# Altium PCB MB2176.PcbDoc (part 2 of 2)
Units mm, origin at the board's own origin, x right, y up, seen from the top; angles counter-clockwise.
Board outline 43 x 47 mm, 2 copper layers (Top Layer, Bottom Layer), stack 0.996 mm thick; 80 components, 70 nets, 345 pads, 549 vias.
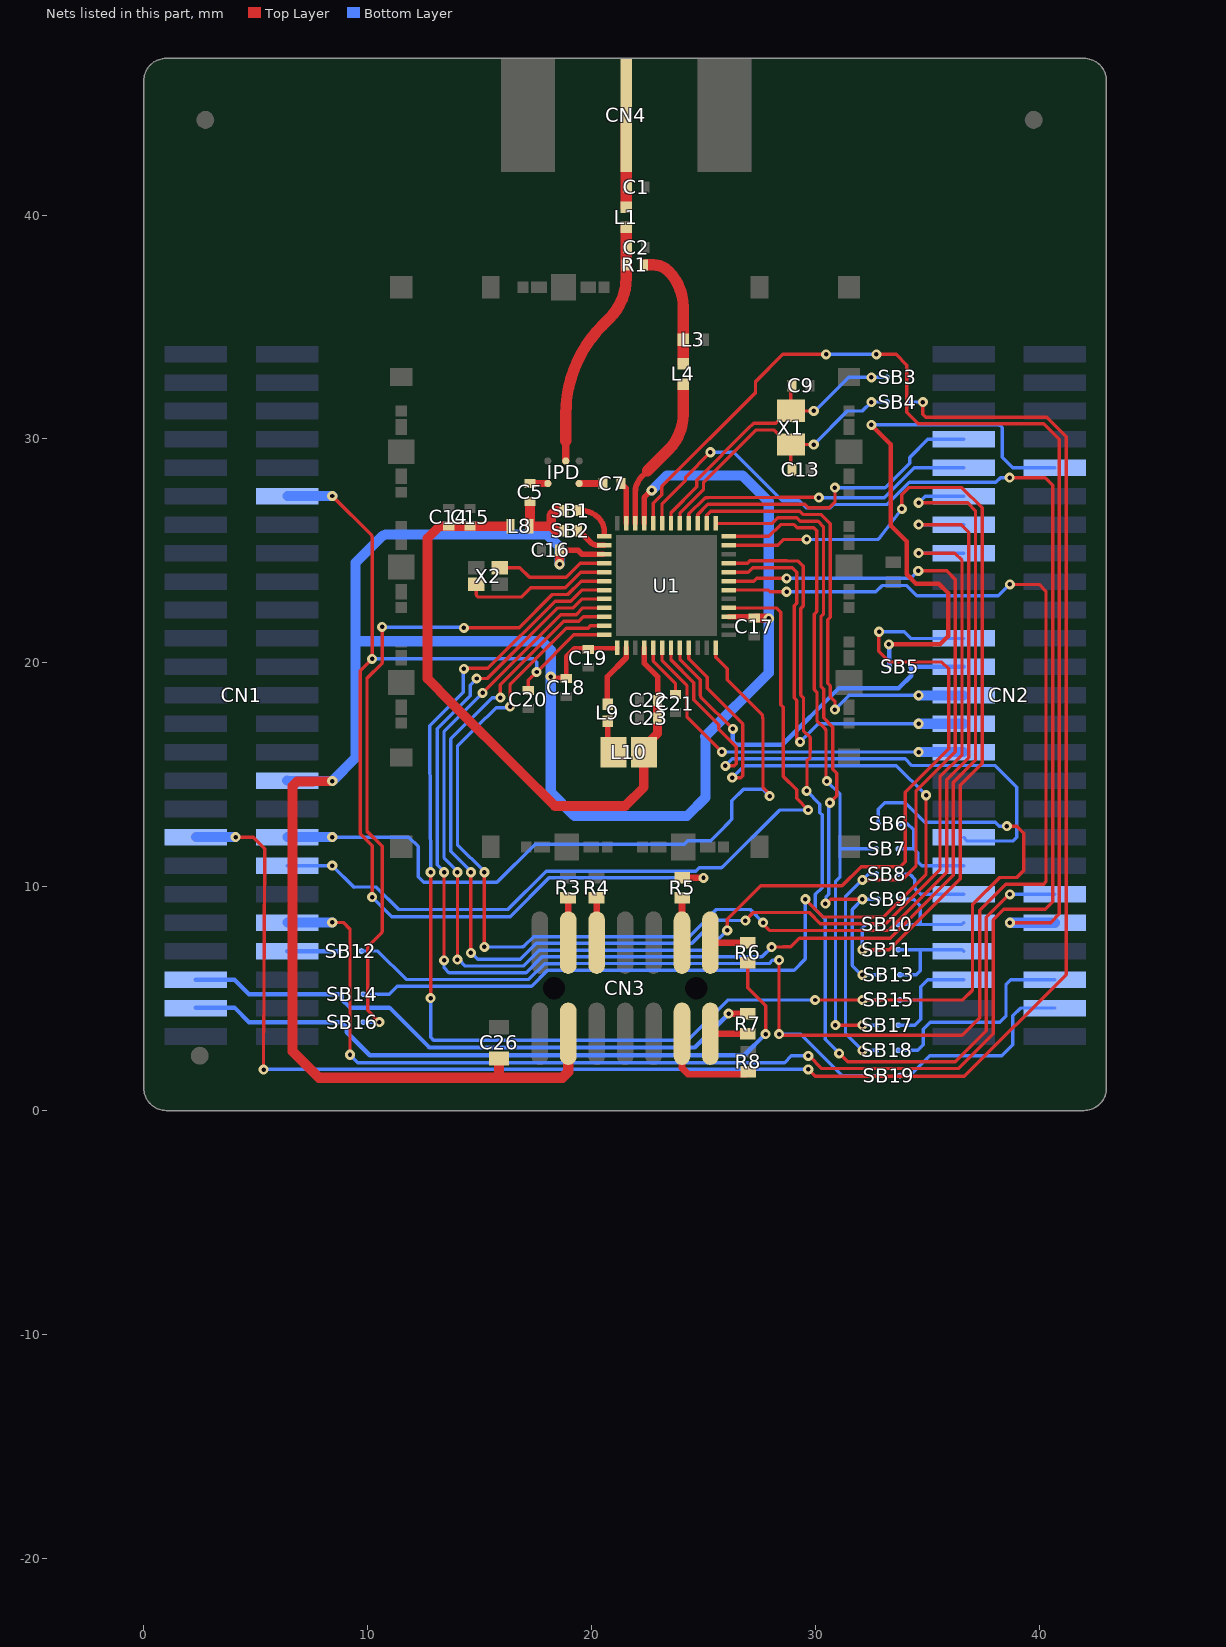
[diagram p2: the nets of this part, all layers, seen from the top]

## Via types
v1: diameter 0.45, hole 0.2, Top Layer to Bottom Layer, tented both sides, 549 vias

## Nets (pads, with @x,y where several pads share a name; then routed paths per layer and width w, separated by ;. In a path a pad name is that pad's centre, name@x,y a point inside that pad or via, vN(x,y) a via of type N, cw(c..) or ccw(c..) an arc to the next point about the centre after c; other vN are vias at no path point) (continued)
GPIO16/OSC32_OUT: CN1.35 SB4.2 | length 83.1
  Top Layer w0.15: v1(4.101,12.21) 4.884,12.21 5.4,11.695 v1(5.35,1.825) ; v1(29.681,1.84) 29.996,1.525 36.65,1.525 41.2,6.075 41.2,30.102 40.327,30.975 34.932,30.975 34.8,31.107 v1(34.8,31.647)
  Bottom Layer w0.15: v1(5.35,1.825) 5.365,1.84 v1(29.681,1.84) ; SB4.2@34.1,31.647 SB4.2@34.175,31.647 v1(34.8,31.647)
  Bottom Layer w0.45: CN1.35@2.343,12.21 v1(4.101,12.21)
GPIO17: CN1.36 U1.48 | length 33.4
  Top Layer w0.15: U1.48@25.55,20.675 25.55,20.25 26.063,19.737 26.063,19.239 27.597,17.705 cw(c27.491,17.599) 27.638,17.623 27.654,17.528 cw(c27.21,17.455) 27.66,17.455 27.66,15.246 27.66,14.417 27.954,14.123 v1(27.954,14.042)
  Bottom Layer w0.15: v1(8.42,12.21) 11.84,12.21 12.254,11.796 12.254,10.439 12.5,10.193 15.778,10.193 17.479,11.894 24.15,11.894 24.299,12.043 25.319,12.043 25.975,12.699 ; v1(27.954,14.042) 27.641,14.355 26.788,14.355 26.268,13.835 26.268,13.011 26.137,12.88 ; 25.975,12.699 26.137,12.861 26.137,12.88 ; 25.975,12.699 25.975,12.718 26.137,12.88
  Bottom Layer w0.45: CN1.36@6.413,12.21 v1(8.42,12.21)
GPIO18: CN1.38 U1.4 | length 37.7
  Top Layer w0.15: U1.4@26.125,22.45 28.25,22.45 28.449,22.251 28.449,18.125 28.56,18.014 28.56,14.921 29.16,14.321 29.16,13.94 v1(29.677,13.424)
  Bottom Layer w0.15: CN1.38@6.413,10.94 v1(8.42,10.94) 9.39,9.97 9.401,9.982 10.385,9.982 11.387,8.98 16.262,8.98 17.976,10.694 24.666,10.694 24.815,10.843 25.753,10.843 ccw(c25.753,10.993) 25.858,10.886 25.901,10.929 ccw(c25.692,11.143) 25.904,10.931 28.397,13.424 v1(29.677,13.424)
GPIO21: CN1.42 U1.19 | length 86.2
  Top Layer w0.15: v1(8.42,8.4) 8.91,8.4 9.211,8.099 v1(9.211,2.491) ; U1.19@23.15,26.225 23.15,27.097 24.2,28.146 24.2,28.297 v1(25.306,29.404) ; v1(29.681,2.44) 29.717,2.44 30.283,1.875 36.375,1.875 37.938,3.438 37.938,8.513 38.413,8.988 40.261,8.988 40.6,9.326 40.6,27.932 40.259,28.273 v1(38.672,28.273)
  Bottom Layer w0.15: v1(9.211,2.491) 9.561,2.14 28.621,2.14 28.921,2.44 v1(29.681,2.44) ; v1(25.306,29.404) 26.36,29.404 28.518,27.246 29.271,27.246 29.592,26.925 30.663,26.925 30.809,27.071 33.21,27.071 34.201,28.062 38.059,28.062 38.269,28.273 v1(38.672,28.273)
  Bottom Layer w0.45: CN1.42@6.413,8.4 v1(8.42,8.4)
GPIO22: CN1.44 SB12.2 | length 2.4
  Bottom Layer w0.2: CN1.44@6.401,7.118 6.408,7.125 SB12.2@8.75,7.125
GPIO23/VCP1_RX: CN1.45 R7.1 SB14.1 | length 26.7
  Top Layer w0.3: v1(26.125,4.325) R7.1@26.975,4.325
  Bottom Layer w0.2: CN1.45@2.331,5.848 4.052,5.848 4.7,5.2 SB14.1@8.825,5.2 8.835,5.19 8.835,4.974 9.211,4.598 10.523,4.598 10.525,4.6 10.975,4.6 12.76,2.815 24.615,2.815 v1(26.125,4.325)
GPIO24/VCP1_TX: CN1.47 R6.2 SB16.1 | length 30.4
  Top Layer w0.15: R6.2@26.975,6.6 26.975,5.478 27.775,4.678 v1(27.775,3.417)
  Bottom Layer w0.2: CN1.47@2.331,4.598 4.052,4.598 4.7,3.95 SB16.1@8.825,3.95 9.063,3.712 9.063,3.496 10.094,2.465 26.824,2.465 v1(27.775,3.417)
GPIO28: CN2.7 U1.15 | length 14.3
  Top Layer w0.15: U1.15@24.75,26.225 24.75,26.624 25.201,27.075 29.534,27.075 29.684,26.925 30.62,26.925 30.875,27.18 v1(30.875,27.821)
  Bottom Layer w0.15: v1(30.875,27.821) 33.111,27.821 34.21,28.921 34.21,29.17 35.018,29.978 CN2.7@36.621,29.978
GPIO29: CN2.9 U1.16 | length 13.5
  Top Layer w0.15: U1.16@24.35,26.225 24.35,26.649 25.032,27.331 ; 25.032,27.332 cw(c25.137,27.224) 25.135,27.374 25.198,27.375 cw(c25.201,27.075) 25.2,27.375 28.448,27.388 30.145,27.388 v1(30.158,27.375)
  Bottom Layer w0.15: v1(30.158,27.375) 30.162,27.371 33.085,27.371 34.422,28.708 CN2.9@36.621,28.708
GPIO30: CN2.10 SB5.1 | length 25
  Top Layer w0.2: v1(32.5,30.625) 33.358,29.767 33.358,26.139 34.075,25.422 34.075,23.952 34.491,23.536 35.51,23.536 35.926,23.119 35.926,21.184 35.564,20.823 v1(33.283,20.823)
  Bottom Layer w0.15: v1(32.5,30.625) 38.166,30.625 cw(c38.166,30.475) 38.273,30.581 38.347,30.506 38.347,29.184 38.824,28.708 CN2.10@40.691,28.708
  Bottom Layer w0.2: v1(33.283,20.823) 33.292,20.814 33.292,19.833 SB5.1@33.3,19.825
GPIO31: CN2.11 U1.32 | length 67.1
  Top Layer w0.15: v1@13.412,10.643 13.412,6.745 13.413,6.744 v1(13.413,6.706) ; v1(14.869,19.299) 15.349,19.299 18.5,22.45 19.19,22.45 19.59,22.85 U1.32@20.575,22.85 ; v1(28.047,7.298) 28.568,7.311 cw(c28.572,7.161) 28.572,7.311 28.9,7.311 29.289,7.7 33.352,7.7 36.164,10.512 36.164,14.653 37.151,15.639 37.151,26.8 36.801,27.15 v1(34.614,27.15)
  Bottom Layer w0.15: v1(13.412,10.643) 13.412,10.679 13.112,10.979 13.112,17.057 14.575,18.52 14.575,19.005 v1(14.869,19.299) ; v1(13.413,6.706) 13.413,6.371 13.631,6.153 17.075,6.153 17.787,6.865 27.615,6.865 v1(28.047,7.298) ; v1(34.614,27.15) 34.902,27.438 CN2.11@36.621,27.438
GPIO33: CN2.13 U1.35 | length 61.6
  Top Layer w0.15: v1(15.212,7.305) v1(15.212,10.643) ; v1(16.366,18.039) 16.375,18.435 ccw(c15.925,18.446) 16.375,18.459 16.36,18.971 cw(c16.51,18.975) 16.404,19.081 18.873,21.55 19.848,21.55 19.948,21.65 U1.35@20.575,21.65 ; v1(27.669,8.395) 27.669,8.321 27.948,8.042 33.27,8.042 35.864,10.636 35.864,14.777 36.851,15.764 36.851,25.841 36.524,26.168 v1(34.614,26.168)
  Bottom Layer w0.15: v1(15.212,10.643) 15.212,10.679 14.012,11.879 14.012,16.267 14.859,17.114 14.859,17.118 15.737,17.996 16.323,17.996 v1(16.366,18.039) ; v1@15.25,7.305 16.896,7.308 ccw(c16.895,7.458) 17.001,7.352 17.415,7.765 24.302,7.765 ccw(c24.302,7.915) 24.408,7.809 25.578,8.98 27.085,8.98 v1(27.669,8.395) ; v1(34.614,26.168) CN2.13@36.621,26.168
GPIO34: CN2.15 U1.34 | length 60.8
  Top Layer w0.15: v1(14.612,7.043) v1(14.612,10.643) ; v1(15.925,18.446) 15.925,19.026 18.749,21.85 19.439,21.85 19.639,22.05 20.075,22.05 U1.34@20.575,22.05 ; v1(26.869,8.488) 27.227,8.845 29.718,8.845 30.221,8.342 33.084,8.342 ccw(c33.084,8.492) 33.19,8.386 35.564,10.761 35.564,14.901 36.551,15.888 36.551,24.57 36.222,24.898 v1(34.614,24.898)
  Bottom Layer w0.15: v1(14.612,10.643) 14.612,10.679 13.712,11.579 13.712,16.596 15.562,18.446 v1(15.925,18.446) ; v1@14.692,7.043 14.692,6.984 14.917,6.759 15.276,6.759 15.282,6.753 16.827,6.753 17.539,7.465 24.488,7.465 25.515,8.492 26.125,8.492 26.13,8.488 v1(26.869,8.488) ; v1(34.614,24.898) CN2.15@36.621,24.898
GPIO37: CN2.21 U1.33 | length 59.8
  Top Layer w0.15: v1(14.012,6.744) v1(14.012,10.643) ; v1(15.138,18.658) 15.138,18.663 18.624,22.15 19.314,22.15 19.614,22.45 U1.33@20.575,22.45 ; v1(26.063,8.042) 26.063,8.541 27.557,10.035 31.188,10.035 32.044,10.891 33.788,10.891 34.012,11.115 34.012,14.214 35.951,16.152 35.951,19.728 35.646,20.033 33.367,20.033 cw(c33.367,20.183) 33.244,20.097 32.833,20.508 32.833,21.373 v1(32.848,21.388)
  Bottom Layer w0.15: v1(14.012,10.643) 14.012,10.679 13.412,11.279 13.412,16.933 v1(15.138,18.658) ; v1@14.083,6.744 14.083,6.73 14.359,6.453 15.112,6.453 15.118,6.459 ccw(c15.158,6.603) 15.158,6.453 16.951,6.453 17.663,7.165 25.186,7.165 v1(26.063,8.042) ; v1(32.848,21.388) 33.965,21.388 34.265,21.088 CN2.21@36.621,21.088
GPIO39: CN2.23 SB5.2 U1.44 | length 17.2
  Top Layer w0.15: U1.44@23.95,20.675 23.95,20.15 24.26,19.84 24.263,19.84 24.7,19.403 24.7,19.4 24.863,19.237 24.863,18.552 ccw(c25.013,18.552) 24.907,18.445 v1(26.31,17.052)
  Bottom Layer w0.2: v1(26.31,17.052) 26.31,16.47 26.44,16.34 28.521,16.34 31.054,18.873 33.725,18.873 34.275,19.423 SB5.2@34.275,19.818 ; SB5.2@34.275,19.825 SB5.2@34.275,19.818 ; CN2.23@36.621,19.818 SB5.2@34.275,19.818
GPIO41: CN2.25 U1.14 | length 20.7
  Top Layer w0.15: U1.14@25.15,26.225 25.15,26.599 25.326,26.775 29.295,26.775 29.445,26.625 30.241,26.625 30.66,26.206 30.66,22.037 30.549,21.926 30.549,19.086 30.67,18.965 30.67,18.482 30.875,18.277 v1(30.875,17.907)
  Bottom Layer w0.15: v1(30.875,17.907) 31.516,18.548 v1(34.614,18.548)
  Bottom Layer w0.45: v1(34.614,18.548) CN2.25@36.621,18.548
GPIO42: CN2.27 U1.8 | length 18.6
  Top Layer w0.15: U1.8@26.125,24.05 26.992,24.05 27.192,24.25 28.61,24.25 28.611,24.248 28.962,24.248 29.16,24.05 29.16,22.665 29.049,22.554 29.049,18.434 29.168,18.315 29.168,16.615 v1(29.318,16.465)
  Bottom Layer w0.15: v1(29.318,16.465) 30.131,17.278 v1(34.614,17.278)
  Bottom Layer w0.45: v1(34.614,17.278) CN2.27@36.621,17.278
GPIO44: CN2.29 U1.42 | length 16.6
  Top Layer w0.15: U1.42@23.15,20.675 23.15,20.101 24.263,18.989 24.263,17.584 v1(25.825,16.022)
  Bottom Layer w0.15: v1(25.825,16.022) 25.832,16.015 34.607,16.015 v1(34.614,16.008)
  Bottom Layer w0.45: v1(34.614,16.008) CN2.29@36.621,16.008
GPIO47: CN2.35 U1.43 | length 25.3
  Top Layer w0.15: U1.43@23.55,20.675 23.55,20.126 24.563,19.113 24.563,18.347 25.675,17.235 25.675,17.041 26.46,16.256 26.46,15.483 26.372,15.395 v1(25.979,15.395)
  Bottom Layer w0.15: v1(25.979,15.395) 26.292,15.708 34.016,15.708 34.314,15.41 38.032,15.41 39,14.442 39,12.214 38.824,12.037 36.782,12.037 CN2.35@36.621,12.198
GPIO49: CN2.37 SB6.2 SB7.1 | length 5
  Bottom Layer w0.15: SB6.2@33.7,12.812 34.114,12.812 34.394,12.532 34.394,11.688 ; SB7.1@33.775,11.688 34.394,11.688 ; CN2.37@36.621,10.928 34.757,10.928 34.569,11.115 34.569,11.512 34.394,11.688
GPIO50: CN2.39 SB8.1 | length 3.5
  Bottom Layer w0.15: SB8.1@33.7,10.563 34.21,10.563 34.275,10.498 34.439,10.334 34.439,9.918 34.699,9.658 CN2.39@36.621,9.658
GPIO51: CN2.40 U1.9 | length 42.2
  Top Layer w0.15: U1.9@26.125,24.45 26.968,24.45 27.068,24.55 28.734,24.55 28.736,24.548 29.222,24.548 29.46,24.31 29.46,22.536 29.349,22.425 29.349,18.558 29.468,18.44 29.468,16.964 29.768,16.664 29.768,16.064 29.76,16.056 29.76,15.762 29.624,15.626 29.624,14.293 v1(29.61,14.279) ; v1(31.056,2.556) 31.394,2.218 ccw(c31.5,2.325) 31.499,2.175 36.251,2.175 37.638,3.562 37.638,8.637 38.659,9.658 v1(38.684,9.658)
  Bottom Layer w0.15: v1(29.61,14.279) 30.2,13.689 30.2,13.308 30.3,13.208 30.3,9.958 30,9.658 30,8.981 30.439,8.542 30.439,3.174 v1(31.056,2.556) ; v1(38.684,9.658) CN2.40@40.691,9.658
GPIO52: CN2.41 SB9.2 SB10.1 | length 4.8
  Bottom Layer w0.15: SB10.1@33.7,8.313 34.687,8.313 ; SB9.2@33.775,9.437 34.394,9.437 34.687,9.144 34.687,8.313 ; CN2.41@36.621,8.388 36.546,8.313 34.687,8.313
GPIO53: CN2.42 U1.20 | length 50.8
  Top Layer w0.15: U1.20@22.75,26.225 22.75,27.121 23.142,27.513 23.142,27.828 cw(c23.292,27.827) 23.185,27.932 27.282,32.029 ; v1(30.475,33.775) 28.539,33.775 27.325,32.561 27.325,32.135 ; v1(32.725,33.775) 33.613,33.775 34.087,33.3 34.087,31.182 34.594,30.675 40.203,30.675 40.9,29.978 40.9,8.779 40.509,8.388 v1(38.684,8.388) ; 27.282,32.029 ccw(c27.175,32.135) 27.325,32.135 ; 27.282,32.029 27.325,32.073 27.325,32.135
  Bottom Layer w0.15: v1(30.475,33.775) v1(32.725,33.775)
  Bottom Layer w0.45: v1(38.684,8.388) CN2.42@40.691,8.388
GPIO54: CN2.43 SB11.1 SB13.2 | length 4.9
  Bottom Layer w0.15: SB11.1@33.7,7.187 34.7,7.187 ; SB13.2@33.775,6.062 34.513,6.062 34.687,6.237 34.687,7.175 34.7,7.187 ; CN2.43@36.621,7.118 36.552,7.187 34.7,7.187
GPIO55: CN2.45 SB15.2 SB17.1 | length 5.5
  Bottom Layer w0.15: SB17.1@33.7,3.812 34.439,3.812 34.7,4.073 34.7,4.95 ; SB15.2@33.775,4.938 34.687,4.938 34.7,4.95 ; CN2.45@36.621,5.848 35.018,5.848 34.7,5.53 34.7,4.95
GPIO56: CN2.46 SB18.1 | length 9.5
  Bottom Layer w0.15: SB18.1@33.7,2.688 34.569,2.688 34.813,2.931 34.813,3.637 35.125,3.95 38.237,3.95 38.517,4.23 38.517,5.642 38.723,5.848 CN2.46@40.691,5.848
GPIO57: CN2.48 SB19.2 | length 8.9
  Bottom Layer w0.15: SB19.2@33.775,1.562 34.218,1.562 35.106,2.45 38.325,2.45 38.817,2.942 38.817,4.233 39.162,4.578 CN2.48@40.691,4.578
NetC1_2: C1.2 CN4.1 L1.2 | length 4.1
  Top Layer w0.51: L1.2@21.55,40.35 21.55,41.25 CN4.1@21.55,44.46
NetC2_2: C2.2 IPD.4 L1.1 R1.2 | length 11.2
  Top Layer w0.32: IPD.4@18.848,29.011 18.848,29.901
  Top Layer w0.51: 18.848,29.921 18.848,31.105 ; 18.849,31.106 cw(c24.472,31.106) 20.496,35.082 20.806,35.392 ccw(c19.01,37.188) 21.55,37.188 21.55,37.775 21.55,38.55 L1.1@21.55,39.45
NetC5_1: C5.1 L8.2 SB1.2 SB2.2 | length 3.6
  Top Layer w0.43: L8.2@17.25,26.1 17.254,26.104 17.254,27.047 C5.1@17.258,27.051 ; L8.2@17.275,26.1 18.193,26.1 ; SB2.2@18.698,25.9 18.393,25.9 18.193,26.1 ; SB1.2@18.724,26.8 18.401,26.8 18.193,26.592 18.193,26.1
NetC5_2: C5.2 IPD.1 | length 0.7
  Top Layer w0.32: C5.2@17.318,28.011 IPD.1@18.049,28.011
NetC7_1: C7.1 U1.23 | length 1.9
  Top Layer w0.25: C7.1@21.359,28.008 21.359,27.983 21.55,27.792 U1.23@21.55,26.225
NetC7_2: C7.2 IPD.2 | length 1
  Top Layer w0.32: IPD.2@19.449,28.011 20.456,28.011 C7.2@20.459,28.008
NetC9_2: C9.2 SB3.1 U1.18 X1.2 | length 14.1
  Top Layer w0.15: U1.18@23.55,26.225 23.55,26.704 24.7,27.854 24.7,28.161 26.988,30.448 27.239,30.7 28.237,30.7 28.35,30.813 28.35,30.825 28.775,31.25 X1.2@28.9,31.25 ; C9.2@28.9,32.375 X1.2@28.9,31.25 ; v1@30.075,31.25 X1.2@28.9,31.25
  Bottom Layer w0.15: v1(29.925,31.25) 30,31.25 31.497,32.747 v1(32.5,32.747) SB3.1@33.2,32.747
NetC13_2: C13.2 SB4.1 U1.17 X1.1 | length 13.6
  Top Layer w0.15: U1.17@23.95,26.225 23.95,26.68 25,27.73 25,28.036 27.364,30.4 28.149,30.4 28.35,30.199 28.35,30.175 28.775,29.75 X1.1@28.9,29.75 ; C13.2@28.9,28.625 X1.1@28.9,29.75 ; v1(29.925,29.75) X1.1@28.9,29.75
  Bottom Layer w0.15: v1(29.925,29.75) 31.422,31.247 32.1,31.247 v1(32.5,31.647) SB4.1@33.2,31.647
NetC21_2: C21.2 U1.41 | length 2.5
  Top Layer w0.15: U1.41@22.75,20.675 22.75,20.077 23.75,19.077 C21.2@23.75,18.625
NetCN3_4: CN3.4 R3.1 | length 2
  Top Layer w0.3: R3.1@18.95,9.5 18.96,9.49 CN3.4@18.96,7.5
NetCN3_6: CN3.6 R4.1 | length 2
  Top Layer w0.3: R4.1@20.225,9.5 20.23,9.495 CN3.6@20.23,7.5
NetCN3_11: CN3.11 R8.2 | length 4.7
  Top Layer w0.3: CN3.11@24.04,3.43 24.04,1.897 24.312,1.625 26.903,1.625 R8.2@27.003,1.725 ; R8.2@26.914,1.814 R8.2@26.928,1.828
NetCN3_12: CN3.12 R5.1 | length 2
  Top Layer w0.3: CN3.12@24.04,7.5 24.04,9.49 R5.1@24.05,9.5
NetCN3_13: CN3.13 R7.2 | length 1.7
  Top Layer w0.3: CN3.13@25.31,3.43 25.315,3.425 R7.2@26.975,3.425
NetCN3_14: CN3.14 R6.1 | length 1.7
  Top Layer w0.3: CN3.14@25.31,7.5 R6.1@26.975,7.5
NetL3_1: L3.1 L4.2 R1.1 | length 5.4
  Top Layer w0.51: R1.1@22.45,37.775 22.766,37.775 cw(c22.766,36.836) 23.43,37.5 cw(c21.813,35.883) 24.1,35.883 L3.1@24.1,34.425 L4.2@24.1,33.375
NetL4_1: L4.1 U1.22 | length 6.9
  Top Layer w0.25: U1.22@21.95,26.225 21.95,27.601 cw(c22.974,27.601) 22.25,28.325 22.5,28.575
  Top Layer w0.51: 22.5,28.575 23.43,29.505 ccw(c21.813,31.122) 24.1,31.122 L4.1@24.1,32.425
NetL9_1: L9.1 U1.38 | length 2.9
  Top Layer w0.25: L9.1@20.725,18.152 20.707,18.17 20.707,19.382 21.55,20.225 U1.38@21.55,20.675
NetL9_2: L9.2 L10.2 | length 1.5
  Top Layer w0.25: L9.2@20.725,17.394 20.725,16.27 L10.2@20.987,16.008
NetSB1_1: SB1.1 U1.25 | length 1.9
  Top Layer w0.25: SB1.1@19.375,26.8 19.528,26.8 cw(c19.528,25.69) 20.312,26.475 cw(c19.679,25.841) 20.575,25.841 U1.25@20.575,25.694
NetSB2_1: SB2.1 U1.26 | length 1.4
  Top Layer w0.25: SB2.1@19.375,25.9 cw(c19.375,25.746) 19.484,25.855 19.945,25.394 ccw(c20.292,25.74) 20.292,25.25 U1.26@20.575,25.25
NetSB6_1: SB6.1 SB15.1 U1.31 | length 67
  Top Layer w0.15: v1(12.812,5.025) v1(12.812,10.643) ; v1(14.301,19.725) 14.324,19.749 15.374,19.749 18.376,22.75 19.066,22.75 19.566,23.25 20.002,23.25 U1.31@20.575,23.25 ; v1(29.989,4.938) 32.033,4.923 ccw(c32.036,5.073) v1(32.1,4.938) ; v1(32.1,4.938) 36.593,4.938 37.017,5.361 37.017,9.192 38.234,10.409 39,10.409 39.312,10.722 39.312,12.386 39,12.699 38.551,12.699 v1(38.55,12.7)
  Bottom Layer w0.15: v1(12.812,5.025) 12.812,3.269 12.941,3.14 24.304,3.14 26.101,4.938 v1(29.989,4.938) ; v1(12.812,10.643) 12.781,16.461 12.781,17.181 14.275,18.675 14.275,19.699 v1(14.301,19.725) ; v1(32.1,4.938) SB15.1@32.8,4.938 ; SB6.1@32.8,12.812 32.8,13.45 33.1,13.75 34.007,13.75 34.884,12.873 38.029,12.873 38.202,12.7 v1(38.55,12.7)
NetSB7_2: SB7.2 SB17.2 U1.12 | length 30.4
  Top Layer w0.15: U1.12@26.125,25.65 27.924,25.65 28.449,26.175 29.047,26.175 29.197,26.025 29.935,26.025 30.06,25.9 30.06,22.288 29.949,22.177 29.949,18.807 30.07,18.686 30.07,17.411 30.431,17.05 cw(c30.325,16.944) 30.475,16.944 30.475,14.749 v1(30.51,14.714) ; v1(30.892,3.814) v1(32.1,3.812)
  Bottom Layer w0.15: v1(30.51,14.714) 31.1,14.124 31.1,11.688 ; v1(30.892,3.814) 30.9,3.822 30.9,10.234 31.1,10.434 31.1,11.688 ; v1(32.1,3.812) SB17.2@32.725,3.812 ; SB7.2@32.725,11.688 31.1,11.688
NetSB8_2: SB8.2 SB18.2 U1.7 | length 36.3
  Top Layer w0.15: U1.7@26.125,23.65 27.251,23.65 27.375,23.774 v1(28.71,23.774) ; v1(32.1,10.3) 33.882,10.3 34.492,10.91 34.492,14.269 36.251,16.028 36.251,23.721 35.867,24.105 v1(34.594,24.105)
  Bottom Layer w0.15: v1(28.71,23.774) 34.264,23.774 v1(34.594,24.105) ; SB18.2@32.725,2.688 v1(32.1,2.688) 31.342,3.445 31.342,9.542 v1(32.1,10.3) 32.363,10.563 SB8.2@32.725,10.563
NetSB9_1: SB9.1 SB13.1 U1.13 | length 29.4
  Top Layer w0.15: U1.13@25.55,26.225 28.075,26.225 28.325,26.475 29.171,26.475 29.321,26.325 30.117,26.325 30.36,26.082 30.36,22.161 30.249,22.05 30.249,18.942 30.37,18.821 30.37,17.535 30.775,17.13 30.775,15.25 30.96,15.064 30.96,14.06 v1(30.65,13.75) ; v1(30.45,9.244) 30.488,9.244 30.681,9.437 v1(32.1,9.437)
  Bottom Layer w0.15: v1(30.45,9.244) 30.476,9.27 30.476,9.544 30.6,9.669 30.6,13.699 v1(30.65,13.75) ; SB13.1@32.8,6.062 v1(32.1,6.062) 32.055,6.062 31.642,6.476 31.642,8.98 v1(32.1,9.437) SB9.1@32.8,9.437
NetSB10_2: SB10.2 SB11.2 U1.11 | length 38.2
  Top Layer w0.15: U1.11@26.125,25.25 28.329,25.25 28.588,25.508 v1(29.61,25.508) ; v1(32.1,7.18) 33.295,7.18 36.464,10.349 36.464,14.529 37.451,15.515 37.451,26.924 36.547,27.828 34.176,27.828 33.86,27.512 v1(33.86,26.875)
  Bottom Layer w0.15: v1(29.61,25.508) 32.735,25.508 ccw(c32.735,25.658) 32.853,25.567 v1(33.86,26.875) ; SB11.2@32.725,7.187 32.721,7.184 32.104,7.184 v1(32.1,7.18) 32.1,8.137 32.275,8.313 SB10.2@32.725,8.313
NetSB12_1: SB12.1 SB19.1 U1.6 | length 73.4
  Top Layer w0.15: U1.6@26.125,23.25 27.897,23.25 27.973,23.174 v1(28.71,23.174) ; v1(28.375,6.715) v1(28.375,3.417) 28.429,3.363 36.55,3.363 37.338,4.15 37.338,8.948 38.498,10.108 40.197,10.108 40.3,10.211 40.3,23.193 39.993,23.5 v1(38.687,23.5)
  Bottom Layer w0.15: SB12.1@9.725,7.125 10.449,7.125 11.721,5.853 17.2,5.853 17.909,6.562 19.074,6.562 19.077,6.565 27.935,6.565 28.075,6.706 v1@28.3,6.715 ; v1(28.375,3.417) 29.341,3.417 31.195,1.562 SB19.1@32.8,1.562 ; v1(28.71,23.174) 32.699,23.174 32.975,23.45 34.075,23.45 34.538,22.988 38.175,22.988 v1(38.687,23.5)
NetSB14_2: SB14.2 U1.45 | length 49.8
  Top Layer w0.15: U1.45@24.35,20.675 24.35,20.177 25.163,19.364 25.163,18.866 26.76,17.268 26.76,14.956 26.672,14.868 v1(26.287,14.868) ; v1(29.55,9.437) 30.345,8.642 33.021,8.642 34.942,10.563 v1(34.942,14.083)
  Bottom Layer w0.15: SB14.2@9.8,5.2 10.975,5.2 11.325,5.55 17.321,5.55 18.033,6.262 21.37,6.262 21.373,6.265 29.047,6.265 29.55,6.769 v1(29.55,9.437) ; v1(26.287,14.868) 26.826,15.408 27.399,15.408 33.617,15.408 v1(34.942,14.083)
NetSB16_2: SB16.2 U1.30 | length 30.2
  Top Layer w0.15: v1(10.525,3.95) 10,4.475 10,7.311 10.605,7.916 ccw(c10.499,8.023) 10.649,8.023 10.649,11.806 9.971,12.485 9.971,19.31 10.649,19.989 v1(10.649,21.6) ; v1(14.301,21.562) 16.764,21.562 18.252,23.05 18.942,23.05 19.542,23.65 U1.30@20.575,23.65
  Bottom Layer w0.15: SB16.2@9.8,3.95 v1(10.525,3.95) ; v1(10.649,21.6) 10.668,21.581 14.282,21.581 v1(14.301,21.562)
NetU1_28: U1.28 X2.3 | length 5.1
  Top Layer w0.15: X2.3@15.905,24.25 16.797,24.25 17.229,23.818 18.861,23.818 19.493,24.45 U1.28@20.575,24.45
NetU1_29: U1.29 X2.1 | length 6.7
  Top Layer w0.15: X2.1@14.855,23.5 14.855,23.025 14.943,22.938 16.866,22.938 17.279,23.35 18.817,23.35 19.517,24.05 U1.29@20.575,24.05
NRST: C20.2 CN1.12 R5.2 U1.36 | length 50.7
  Top Layer w0.15: v1(8.42,27.45) 10.155,25.715 ; 10.156,25.714 cw(c10.048,25.609) 10.198,25.609 10.199,20.938 v1(10.199,20.175) 9.671,19.647 9.671,12.36 10.199,11.832 v1(10.199,9.532) ; C20.2@17.172,18.802 17.172,19.213 v1(17.547,19.588) 19.209,21.25 U1.36@20.575,21.25
  Top Layer w0.3: R5.2@24.25,10.505 R5.2@24.05,10.4 24.053,10.397 24.998,10.397 v1(25.002,10.393)
  Bottom Layer w0.15: v1(10.199,9.532) 11.075,8.655 16.362,8.655 18.101,10.394 23.85,10.394 v1(25.002,10.393) ; v1(10.199,20.175) 11.829,20.175 ; 11.83,20.175 11.856,20.175 ccw(c11.858,20.325) 11.859,20.175 11.885,20.175 ; 11.886,20.175 17.397,20.175 17.547,20.025 v1(17.547,19.588)
  Bottom Layer w0.45: CN1.12@6.413,27.45 v1(8.42,27.45)
VDD: C16.2 C17.2 C18.2 C19.2 C26.2 CN1.32 CN3.3 U1.3 U1.21 U1.27 U1.37 | length 106.6
  Top Layer w0.2: v1(18.18,19.379) 18.192,19.285 cw(c18.316,19.161) 18.316,19.336 18.695,19.336 C18.2@18.874,19.339 ; C18.2@18.875,19.34 18.875,20.296 19.23,20.65 21.15,20.65 U1.37@21.15,20.675
  Top Layer w0.25: C16.2@18.575,25.025 19.4,25.025 19.575,24.85 U1.27@20.525,24.85 ; U1.21@22.35,26.225 22.35,27.38 22.669,27.699 v1(22.692,27.699) ; U1.3@26.125,22.05 27.185,22.05 C17.2@27.31,22
  Top Layer w0.3: v1@27.895,22 v1(27.915,21.98) 27.935,21.96 v1@27.935,22
  Top Layer w0.4: v1(18.575,24.4) C16.2@18.575,25.025 ; C17.2@27.31,22 v1@27.895,22
  Top Layer w0.45: v1(8.42,14.711) 7.557,14.697 6.847,14.697 6.65,14.5 6.65,2.64 7.825,1.465 15.875,1.465 ; C26.2@15.875,2.325 15.875,1.465 ; CN3.3@18.96,3.43 18.96,1.733 18.692,1.465 15.875,1.465
  Bottom Layer w0.45: CN1.32@6.401,14.738 7.571,14.711 v1(8.42,14.711) 9.461,15.752 9.461,20.962 ; v1(18.575,24.4) 18.575,25.167 18.017,25.725 10.841,25.725 ccw(c10.841,25.425) 10.629,25.637 9.461,24.47 9.461,20.962 ; v1(22.692,27.699) 23.367,28.375 26.735,28.375 27.915,27.195 v1(27.915,21.98) 27.915,19.548 25.08,16.713 ; 25.786,17.419 25.1,16.733 25.1,13.994 24.264,13.159 19.233,13.159 18.18,14.212 v1(18.18,19.379) 18.18,20.57 17.876,20.874 ccw(c17.664,20.662) 17.664,20.962 9.461,20.962
VFBSD: C14.1 C15.2 C22.2 C23.1 L8.1 L10.1 U1.40 | length 29
  Top Layer w0.25: U1.40@22.35,20.675 22.35,19.982 22.951,19.381 C22.2@22.951,18.322
  Top Layer w0.4: L10.1@22.376,16.275 22.95,16.85 C22.2@22.95,18.321
  Top Layer w0.43: L8.1@16.325,26.1 C15.2@14.575,26.1 C14.1@13.625,26.1 13.21,26.1 12.674,25.564 12.674,19.29 13.729,18.235 16.749,15.215 18.363,13.601 21.5,13.601 22.339,14.439 L10.1@22.339,16.008
pads on no net: CART-1.1 CN1.2 CN1.3 CN1.4 CN1.5 CN1.8 CN1.10 CN1.11 CN1.16 CN1.18 CN1.19 CN1.20 CN1.21 CN1.23 CN1.27 CN1.30 CN1.39 CN1.41 CN1.43 CN1.48 CN1.50 CN2.1 CN2.3 CN2.4 CN2.5 CN2.6 CN2.12 CN2.16 CN2.17 CN2.18 CN2.19 CN2.22 CN2.24 CN2.28 CN2.30 CN2.31 CN2.33 CN2.34 CN2.36 CN2.47 CN2.49 CN3.1 CN3.2 CN3.8 CN3.9 CN3.10 CN3.NPTH1 CN3.NPTH2 MIRE-1.1 MIRE-2.1 MIRE-3.1 MIRE-4.1 MIRE-5.1

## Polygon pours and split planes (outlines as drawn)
GND on Top Layer "GND_L01_P001" (solid, remove dead copper, pour order 1): 0,47 43,47 43,0 0,0
GND on Top Layer "GND_L01_P004" (solid, remove dead copper, pour order 4): 14.496,29.375 14.5,29.371 14.5,27.35 14.787,27.063 16.625,27.063 16.625,29.375
GND on Bottom Layer "GND_L02_P003" (solid, remove dead copper, pour order 3): 0,47 43,47 43,0 0,0

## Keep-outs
Top Layer:
  region: 25.3,34.959 26.091,34.959 cw(c26.091,34.425) 26.625,34.425 cw(c26.1,34.425) 26.1,33.9 25.509,33.9 25.3,33.9
  region: 14.155,23.87 14.08,23.87 cw(c14.08,24.25) 13.7,24.25 cw(c14.075,24.25) 14.075,24.625 15.225,24.625 15.225,23.875
  region: 13.091,26.75 13.091,28.091 cw(c13.625,28.091) 13.625,28.625 cw(c13.625,28.1) 14.15,28.1 14.15,26.75 14,26.75
  region: 14.041,26.75 14.041,28.091 cw(c14.575,28.091) 14.575,28.625 cw(c14.575,28.1) 15.1,28.1 15.1,26.75 14.95,26.75
  region: 15.954,24.804 19.448,24.804 19.448,25.74 15.954,25.74

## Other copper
Top Layer:
  pour cut-out: 22.45,37.395 22.766,37.395 cw(c22.766,36.836) 23.161,37.231 ccw(c31.27,45.302) 23.162,37.23 cw(c21.813,35.883) 23.72,35.883 23.72,32.425 24.48,32.425 24.48,35.883 ccw(c21.813,35.883) 23.699,37.769 ccw(c22.766,36.836) 22.766,38.155 22.45,38.155
  pour cut-out: 18.468,29.921 18.468,31.105 cw(c18.848,31.105) 18.468,31.128 cw(c24.472,31.106) 20.227,35.351 20.537,35.661 20.536,35.661 20.537,35.661 ccw(c19.01,37.188) 21.17,37.188 21.17,39.45 21.93,39.45 21.93,37.188 cw(c19.01,37.188) 21.075,35.123 20.765,34.813 cw(c17.174,38.412) 20.764,34.812 cw(c20.902,34.674) 20.765,34.813 20.764,34.812 ccw(c24.472,31.106) 19.229,31.106 cw(c18.849,31.106) 19.228,31.084 19.228,29.921
  pour cut-out: 21.706,29.901 21.706,26.8 16.521,26.8 16.521,29.901 18.131,29.901 18.131,29.666 19.57,29.666 19.57,29.901
  pour cut-out: 18.14,18.401 16,18.402 16,19.411 18.156,19.434
  pour cut-out: 18.163,18.653 19.532,18.653 19.532,16.072 18.163,16.072
  pour cut-out: 19.423,17.403 19.423,15.072 24.25,15.072 24.25,17.369
  region net GND: 22.351,18.663 21.207,18.663 21.207,17.063 22.35,17.063
  region net GND: 24.98,33.891 24.48,33.891 24.48,33.395
  region net GND: 21.93,37.395 21.93,37.377 22.329,37.377 22.347,37.395
  pour cut-out: 22.45,38.155 21.948,38.155 21.93,38.155 21.93,37.395 22.45,37.395
  region net GND: 21.93,37.213 22.139,37.213 22.19,37.213 22.354,37.377 21.93,37.377
  region net GND: 21.92,36.942 21.923,36.971 21.93,37.213 22.154,37.213 22.161,37.219
  region net GND: 21.93,38.612 21.93,38.173 22.45,38.173
  region net GND: 24.48,35.455 24.48,34.959 24.503,34.959
  pour cut-out: 21.17,37.213 21.17,47 21.93,47 21.93,37.213
  region net NetC2_2: 18.611,29.826 18.623,29.799 18.688,29.666 18.851,29.666 18.852,29.665 19.009,29.665 19.071,29.799 19.084,29.826
  region net GND: 18.176,28.283 18.199,28.271 18.221,28.257 18.242,28.241 18.261,28.224 18.279,28.204 18.295,28.183 18.309,28.161 18.321,28.138 18.331,28.114 18.339,28.089 18.344,28.063 18.348,28.038 18.349,28.011 18.349,27.686 19.149,27.686 19.149,28.011 19.15,28.038 19.154,28.063 19.159,28.089 19.167,28.114 19.177,28.138 19.189,28.161 19.203,28.183 19.219,28.204 19.237,28.224 19.256,28.241 19.277,28.257 19.299,28.271 19.322,28.283 19.346,28.293 19.371,28.301 19.397,28.307 19.423,28.31 19.449,28.311 19.774,28.311 19.774,28.511 20.524,28.511 20.524,29.636 19.148,29.636 19.148,29.011 19.147,28.985 19.144,28.959 19.138,28.934 19.13,28.909 19.12,28.885 19.108,28.861 19.094,28.839 19.078,28.819 19.06,28.799 19.041,28.782 19.02,28.766 18.998,28.752 18.975,28.74 18.951,28.729 18.926,28.722 18.9,28.716 18.874,28.713 18.848,28.711 18.822,28.713 18.796,28.716 18.77,28.722 18.745,28.729 18.721,28.74 18.698,28.752 18.676,28.766 18.655,28.782 18.636,28.799 18.618,28.819 18.602,28.839 18.588,28.861 18.576,28.885 18.566,28.909 18.558,28.934 18.553,28.959 18.549,28.985 18.548,29.011 18.548,29.636 16.974,29.636 16.974,28.511 17.724,28.511 17.724,28.311 18.049,28.311 18.075,28.31 18.101,28.307 18.127,28.301 18.152,28.293
  pour cut-out: 16.63,26.371 15.094,26.371 15.094,26.759 16.63,26.759
  region net GND: 19.228,30.378 19.228,29.901 19.71,29.901
  region net GND: 17.867,29.901 18.468,29.901 18.468,30.565
  pour cut-out: 21.711,29.301 21.711,29.902 23,29.902 23,29.301
  pour cut-out: 13.865,24.825 13.617,24.577 13.617,23.738 14.647,22.708 15.261,22.708 15.261,24.823
  pour cut-out: 28.5,32.938 28.588,33.025 30.193,33.025 30.309,32.909 30.309,28.089 30.313,28.085 30.29,28.062 28.128,28.062 27.924,28.266 27.924,32.362

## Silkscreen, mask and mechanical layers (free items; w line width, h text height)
Top Overlay:
  lines w0.12: 19.713,27.001 20.067,27.355 22.374,27.355 ; 19.774,25.964 20.024,26.214 20.024,26.535 20.378,26.889 25,26.889
  text "J" at 31.675,41.686 h10
  text "MB2176A" at 30.963,39.013 h2.3
  text "H" at 7.912,38.4 h10
  text "K" at 2.052,38.289 h8
  text "RX_WAKEUP" at 24.9,37.741 h1.3
  text "E" at 7.539,6.607 h9
  text "C" at 1.36,6.215 h8
  text "I" at 36.886,3.613 h10
Top Solder:
  region: 19.198,29.336 19.418,29.336 19.418,29.586 19.198,29.586
  region: 18.738,29.336 18.958,29.336 18.958,29.586 18.738,29.586
  region: 18.278,29.336 18.498,29.336 18.498,29.586 18.278,29.586
  region: 20.151,28.461 20.574,28.461 20.574,29.121 20.151,29.121
  region: 16.928,28.461 17.351,28.461 17.351,29.121 16.928,29.121
M1-Board Shape:
  the board outline again, w0.1
Mechanical 11:
  drawing of 4390 lines, arcs and shapes, not listed
  text "Generated with the LayoutEditor (This message will NOT added in any commercial version of the LayoutEditor.)" at 11.25,33.429 h0
  text "Generated with the LayoutEditor (This message will NOT added in any commercial version of the LayoutEditor.)" at 10.756,23.078 h0 r90
Drill Drawing:
  drawing of 166 lines, arcs and shapes, not listed
  text "PCB SPECIFICATIONS :" at -22.541,97.137 h3
  text "TG-150" at 51.675,93.175 h3
  text "A.   MATERIAL :" at -22.541,93.137 h3
  text "FR-4" at 15.959,93.137 h3
  text "TG-170" at 32.459,93.137 h3
  text "X   TG-140" at 66.1,93.1 h3
  text "B.   MATERIAL FAMILY :" at -22.541,90.137 h3
  text "VT-47" at 15.959,90.137 h3
  text "C.   SOLDERMASK COLOR :" at -22.541,87.137 h3
  text "GREEN" at 15.959,87.137 h3
  text "X  BLUE" at 32.459,87.137 h3
  text "RED" at 50.709,87.137 h3
  text "BLACK" at 66.709,87.137 h3
  text "D.   SILKSCREEN COLOR :" at -22.541,84.137 h3
  text "X  WHITE" at 15.959,84.137 h3
  text "YELLOW" at 32.459,84.137 h3
  text "BLACK" at 50.709,84.137 h3
  text "E.   SURFACE FINISH :" at -22.541,81.137 h3
  text "X  ENIG" at 15.959,81.137 h3
  text "IMMERSION SILVER" at 32.459,81.137 h3
  text "IMMERSION TIN" at 66.709,81.137 h3
  text "HASL" at 15.959,78.137 h3
  text "HASL (PB-FREE)" at 32.459,78.137 h3
  text "GOLDEN FINGER" at 66.709,78.137 h3
  text "F.   IMPEDANCE CONTROL :" at -22.541,75.137 h3
  text "NO" at 15.959,75.137 h3
  text "X  YES" at 32.459,75.137 h3
  text "G.   THROUGH VIA :" at -22.541,72.137 h3
  text "PLUG THE VIAS WHICH ARE COVERED WITH SOLDERMASK ONE OR TWO SIDE." at 15.959,72.137 h3
  text "PLUG MATERIAL :" at 15.959,69.137 h3
  text "X  SOLDERMASK" at 41.459,69.137 h3
  text "NON-CONDUCTIVE EPOXY." at 66.709,69.137 h3
  text "H.   STACK-UP :" at -22.541,66.137 h3
  text "SEE LAYER STACK-UP SEQUENCE FOR OVERALL THICKNESS." at 15.959,66.137 h3
  text "PCB : TYPE 3" at 110.088,57.996 h3
  text "ASPECT-RATIO, AXE Z :" at 110.088,52.496 h3
  text "6 :1 à 8 :1 / LEVEL \"B\"" at 110.107,45.749 h3
  text "Layer" at 50.841,44.7 h1.8
  text "Name" at 58.372,44.7 h1.8
  text "Material" at 72.928,44.7 h1.8
  text "Thickness" at 86.013,44.7 h1.8
  text "Constant" at 96.758,44.7 h1.8
  text "Top Overlay" at 58.372,41.1 h1.8
  text "Top Solder" at 58.372,37.5 h1.8
  text "Solder Resist" at 72.928,37.5 h1.8
  text "0.010mm" at 86.013,37.5 h1.8
  text "3.5" at 96.758,37.5 h1.8
  text "1" at 50.841,33.9 h1.8
  text "Top Layer" at 58.372,33.9 h1.8
  text "Copper" at 72.928,33.9 h1.8
  text "0.041mm" at 86.013,33.9 h1.8
  text "MINIMUN PARAMETERS" at 109.5,32.02 h3
  text "Dielectric 2" at 58.372,30.3 h1.8
  text "FR4" at 72.928,30.3 h1.8
  text "0.914mm" at 86.013,30.3 h1.8
  text "4.3" at 96.758,30.3 h1.8
  text "2" at 50.84,26.7 h1.8
  text "Bottom Layer" at 58.372,26.7 h1.8
  text "Copper" at 72.928,26.7 h1.8
  text "0.041mm" at 86.013,26.7 h1.8
  text "DEFAULT" at 109.5,26.52 h3
  text "Bottom Solder" at 58.372,23.1 h1.8
  text "Solder Resist" at 72.928,23.1 h1.8
  text "0.010mm" at 86.013,23.1 h1.8
  text "3.5" at 96.758,23.1 h1.8
  text "TRACKS : 0.150mm           / GAPS : 0.150mm" at 109.5,20.77 h3
  text "Bottom Overlay" at 58.372,19.5 h1.8
  text "Symbol" at 51.124,12.705 h2.16
  text "Count" at 59.578,12.705 h2.16
  text "Hole Size" at 68.346,12.705 h2.16
  text "Plated" at 83.766,12.705 h2.16
  text "Hole Type" at 91.191,12.705 h2.16
  text "Drill Layer Pair" at 101.995,12.705 h2.16
  text "Via/Pad" at 122.464,12.705 h2.16
  text "Hole Length" at 131.319,12.705 h2.16
  text "549" at 59.578,8.977 h1.8
  text "0.20mm (7.87mil)" at 68.346,8.977 h1.8
  text "PTH" at 83.766,8.977 h1.8
  text "Round" at 91.191,8.977 h1.8
  text "Top Layer - Bottom Layer" at 101.995,8.977 h1.8
  text "Via" at 122.464,8.977 h1.8
  text "-" at 131.319,8.977 h1.8
  text "2" at 59.578,5.249 h1.8
  text "1.00mm (39.37mil)" at 68.346,5.249 h1.8
  text "NPTH" at 83.766,5.249 h1.8
  text "Round" at 91.191,5.249 h1.8
  text "Top Layer - Bottom Layer" at 101.995,5.249 h1.8
  text "Pad" at 122.464,5.249 h1.8
  text "-" at 131.319,5.249 h1.8
  text "551 Total" at 59.578,1.522 h1.8

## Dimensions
1,0 to 1,47 on M2-Board Dimensions
0,1 to 43,1 on M2-Board Dimensions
